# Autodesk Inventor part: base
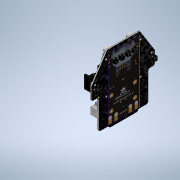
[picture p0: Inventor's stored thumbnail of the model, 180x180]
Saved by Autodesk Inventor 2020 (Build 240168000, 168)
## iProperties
Part Number: base
Material: Générique
Document SubType Name: Modeling
Designer: Buhl
Density: 1 g/cm^3
Appearance: Par défaut
Author: Buhl
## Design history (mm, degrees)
sketch "Esquisse1"
  geometry: L1 (0, 0)-(78, 0); L2 (78, -3)-(78, -44); L3 (14.627, -47)-(3, -47); L4 (0, -44)-(0, -3); L5 (-3, 0)-(-8.5, 0); L6 (-11.5, 3)-(-11.5, 19.102); L7 (-11.5, 20)-(88.5, 20); L8 (88.5, 19.135)-(88.5, 3); L9 (62.948, 58)-(15.117, 58); L10 (12.611, 56.649)-(-11.006, 20.75); L11 (88.04, 20.732)-(65.487, 56.597); L12 (81, 0)-(85.5, 0); L13 (18.5, -50)-(59.768, -50); L14 (75, -47)-(63.625, -47.035); A1 r 2 centre (86.5, 19.423) between (88.5, 19.423) and (88.193, 20.488); A2 r 2 centre (63.5, 56) between (65.193, 57.065) and (63.5, 58); A3 r 2 centre (14.578, 56) between (14.578, 58) and (12.907, 57.099); A4 r 2 centre (-9.5, 19.401) between (-11.171, 20.5) and (-11.5, 19.401); A5 r 2 centre (-9.5, 2) between (-11.5, 2) and (-9.5, 0); A6 r 3 centre (85.5, 19.135) between (88.5, 19.135) and (88.04, 20.732); A7 r 3 centre (62.948, 55) between (65.487, 56.597) and (62.948, 58); A8 r 3 centre (15.117, 55) between (15.117, 58) and (12.611, 56.649); A9 r 3 centre (-8.5, 19.102) between (-11.006, 20.75) and (-11.5, 19.102); A10 r 3 centre (-8.5, 3) between (-11.5, 3) and (-8.5, 0); A11 r 3 centre (-3, -3) between (0, -3) and (-3, 0); A12 r 3 centre (3, -44) between (0, -44) and (3, -47); A13 r 3 centre (75, -44) between (75, -47) and (78, -44); A14 r 3 centre (81, -3) between (81, 0) and (78, -3); A15 r 3 centre (85.5, 3) between (85.5, 0) and (88.5, 3); A16 r 2 centre (14.627, -49) between (16.564, -48.5) and (14.627, -47); A17 r 2 centre (63.632, -49.035) between (63.625, -47.035) and (61.7, -48.518); A18 r 2 centre (18.5, -48) between (16.564, -48.5) and (18.5, -50); A19 r 2 centre (59.768, -48) between (59.768, -50) and (61.7, -48.518); 8 further points
  constraints: 38 point on circle, 36 tangent, 33 point on line, 28 end point, 19 centre point, 14 equal radius, 4 horizontal, 4 parallel, 2 perpendicular
  dimensions: "d0" = 78 distance of point (78, -47) point (0, -47); "d1" = 47 distance of L1.end point (78, -47); "d2" = 100 distance of L7.start L7.end; "d3" = 11.5 distance between parallel lines of L6 L4; "d4" = 20 distance of point (-11.5, 0) L7.start; "d5" = 105 distance between parallel lines of L3 L9; "d6" = 50 distance of point (63.5, 58) point (13.5, 58); "d7" = 25 distance from line of point (13.5, 58) L6; "d8" = 2 radius of A1 (derived); "d9" = 3 radius of A6; "d10" = 3 radius of A14 (derived); "d247" = 3 distance between parallel lines of L3 L13; "d249" = 2 radius of A16 (derived)
extrude "Extrusion1" new body sketch "Esquisse1" distance "d11" = 1.6; taper "d12" = 0 deg
sketch "Esquisse2"
  geometry: L1 (-47, 3)-(-47, 75) reference; L2 (-44, 78)-(-3, 78) reference; L3 (-47, 3)-(-47, 75) reference; L4 (-47, 39)-(32.996, 39); L5 (-50, 18.5)-(-50, 59.768) reference; L6 (0, 81)-(0, 85.5) reference; L7 (3, 88.5)-(19.135, 88.5) reference; L8 (58, 62.948)-(58, 15.117) reference; L9 (20.732, 88.04)-(56.597, 65.487) reference; C1 r 1.5 at (19.402, 83.5); C2 r 1.5 at (46, 66.244); C3 r 1.5 at (-5, 66); C4 r 1.5 at (-32, 39); 3 further points
  constraints: 4 centre point, 2 end point, 1 horizontal, 1 midpoint, 1 point on line
  dimensions: "d13" = 3 diameter of C1; "d16" = 3 diameter of C2; "d18" = 3 diameter of C3; "d255" = 3 diameter of C4; "d256" = 18 distance from line of L5 C4.centre; "d257" = 12 distance from line of L2 C3.centre; "d258" = 5 distance from line of C3.centre L6; "d259" = 5 distance from line of L7 C1.centre; "d260" = 12 distance from line of L8 C2.centre; "d261" = 5 distance from line of L9 C2.centre
extrude "Extrusion2" cut sketch "Esquisse2" distance "d21" = 1.6; taper "d22" = 0 deg
sketch "Esquisse3"
  geometry: C1 r 1.5 at (-5, 66) reference; C2 r 1.5 at (46, 66.244) reference; C3 r 1.5 at (19.402, 83.5) reference; C4 r 2.75 at (-5, 66); C5 r 2.75 at (46, 66.244); C6 r 1.5 at (19.402, 83.5) reference; C7 r 2.75 at (19.402, 83.5); C8 r 1.5 at (-32, 39) reference; C9 r 2.75 at (-32, 39); 1 further point
  constraints: 4 centre point, 4 coincident
  dimensions: "d23" = 5.5 diameter of C4; "d24" = 5.5 diameter of C5; "d25" = 5.5 diameter of C7; "d262" = 5.5 diameter of C9
extrude "Extrusion3" join sketch "Esquisse3" distance "d26" = 3; taper "d27" = 0 deg
sketch "Esquisse4"
  geometry: L1 (-26, 10.532)-(-32, 10.532); L2 (-32, 10.532)-(-32, 67.532); L3 (-32, 67.532)-(-26, 67.532); L4 (-26, 67.532)-(-26, 10.532); L5 (-58, 62.948)-(-58, 15.117) reference; L6 (-3.465, 3.627)-(-1.465, 3.627); L7 (-1.465, 3.627)-(-1.465, 54.627); L8 (-1.465, 54.627)-(-3.465, 54.627); L9 (-3.465, 54.627)-(-3.465, 3.627); L10 (-58, 39.032)-(-14.636, 39.032); 2 further points
  constraints: 18 end point, 4 parallel, 3 horizontal, 2 midpoint, 2 perpendicular, 1 point on line
  dimensions: "d28" = 32 distance between parallel lines of L4 L5; "d29" = 6 distance of L2.end L3.end; "d30" = 51 distance of L8.end L6.start; "d31" = 57 distance between parallel lines of L3 L1; "d32" = 2 distance between parallel lines of L7 L9
extrude "Extrusion4" join sketch "Esquisse4" distance "d33" = 12.2; taper "d34" = 0 deg
sketch "Esquisse5"
  geometry: 1 further point
sketch "Esquisse6"
  geometry: 1 further point
node "Plan de construction1"
node "Plan de construction3"
mirror "Symétrie1"
sketch "Esquisse9"
  geometry: L1 (-3, 0)-(-44, 0) reference; L2 (-32, 0)-(-17, 0); L3 (-17, 0)-(-17, 24); L4 (-17, 24)-(-32, 24); L5 (-32, 24)-(-32, 0); L6 (-47, 3)-(-47, 75) reference; 1 further point
  constraints: 8 end point, 2 parallel, 1 horizontal, 1 perpendicular, 1 point on line
  dimensions: "d54" = 15 distance of L4.end L3.end; "d55" = 24 distance of L3.end L2.end; "d56" = 15 distance between parallel lines of L6 L5
extrude "Extrusion8" join sketch "Esquisse9" distance "d57" = 11; taper "d58" = 0 deg
sketch "Esquisse10"
  geometry: L1 (0, 12)-(-11, 12) reference; L2 (0, 12)-(0, 27) reference; L3 (-11, 12)-(0, 27); C1 r 1.5 at (-5.5, 19.5); 1 further point
  constraints: 2 end point, 1 centre point, 1 midpoint
  dimensions: "d59" = 3 diameter of C1
extrude "Extrusion9" cut sketch "Esquisse10" distance "d60" = 10; taper "d61" = 0 deg
sketch "Esquisse11"
  geometry: L1 (-36, 41.532)-(-42, 41.532); L2 (-42, 41.532)-(-42, 46.532); L3 (-42, 46.532)-(-36, 46.532); L4 (-36, 46.532)-(-36, 41.532); L5 (-58, 62.948)-(-58, 15.117) reference; L6 (-15, 82.5)-(-9, 82.5); L7 (-9, 82.5)-(-9, 87.5); L8 (-9, 87.5)-(-15, 87.5); L9 (-15, 87.5)-(-15, 82.5); L10 (0, 81)-(0, 85.5) reference; L11 (-3, 88.5)-(-19.135, 88.5) reference; L12 (-61.191, 39.032)-(-11.173, 39.032); L13 (-42, 51.532)-(-36, 51.532); L14 (-36, 51.532)-(-36, 56.532); L15 (-36, 56.532)-(-42, 56.532); L16 (-42, 56.532)-(-42, 51.532); 2 further points
  constraints: 26 end point, 6 parallel, 4 horizontal, 3 perpendicular, 1 midpoint, 1 point on line
  dimensions: "d63" = 5 distance of L1.end L2.end; "d64" = 6 distance of L2.end L3.end; "d65" = 22 distance between parallel lines of L4 L5; "d271" = 6 distance of L7.end L8.end; "d272" = 5 distance of L6.end L7.end; "d273" = 9 distance between parallel lines of L10 L7; "d274" = 6 distance between parallel lines of L11 L6; "d275" = 2.5 distance between parallel lines of L1 L12; "d276" = 6 distance of L15.end L14.end; "d277" = 5 distance of L14.end L13.end; "d278" = 5 distance between parallel lines of L13 L3
extrude "Extrusion10" join sketch "Esquisse11" distance "d66" = 5; taper "d67" = 0 deg
mirror "Symétrie3"
sketch "Esquisse13"
  geometry: L1 (-52.453, 14.685)-(-52.453, 64.242); L2 (-52.453, 64.242)-(45.75, 64.242); L3 (45.75, 64.242)-(45.75, 14.685); L4 (45.75, 14.685)-(-52.453, 14.685); 1 further point; 1 other entity
  constraints: 2 other
  node "Image1"
sketch "Esquisse14"
  geometry: L1 (42.128, 71.823)-(42.128, 5.773); L2 (42.128, 5.773)-(-45.058, 5.773); L3 (-45.058, 5.773)-(-45.058, 71.823); L4 (-45.058, 71.823)-(42.128, 71.823); 1 further point; 1 other entity
  constraints: 2 end point, 1 other
  node "Image2"
sketch "Esquisse16"
  geometry: L1 (-32, 24)-(-32, 0) reference; L2 (-32, 0)-(-17, 0) reference; L3 (-32, 0)-(-29.5, 0); L4 (-29.5, 0)-(-29.5, 7); L5 (-29.5, 7)-(-32, 7); L6 (-32, 7)-(-32, 0); L7 (-17, 0)-(-19.5, 0); L8 (-19.5, 0)-(-19.5, 7); L9 (-19.5, 7)-(-17, 7); L10 (-17, 7)-(-17, 0); L11 (-32, 54)-(-32, 78) reference; L12 (-32, 78)-(-17, 78) reference; L13 (-17, 78)-(-17, 54) reference; L14 (-32, 78)-(-29.5, 78); L15 (-29.5, 78)-(-29.5, 71); L16 (-29.5, 71)-(-32, 71); L17 (-32, 71)-(-32, 78); L18 (-17, 78)-(-19.5, 78); L19 (-19.5, 78)-(-19.5, 71); L20 (-19.5, 71)-(-17, 71); L21 (-17, 71)-(-17, 78); 1 further point
  constraints: 32 end point, 8 parallel, 4 horizontal, 4 perpendicular, 2 point on line
  dimensions: "d186" = 2.5 distance of L4.end L5.end; "d187" = 2.5 distance of L8.end L9.end; "d188" = 7 distance of L3.end L4.end; "d189" = 7 distance of L18.end L19.end
extrude "Extrusion13" cut sketch "Esquisse16" distance "d190" = 11; taper "d191" = 0 deg
node "Plan de construction2"
sketch "Esquisse12"
  geometry: C1 r 1.683 at (-14.287, 36.5); C2 r 1.703 at (-9.745, 36.5); 1 further point
  constraints: 2 centre point
extrude "Extrusion11" cut sketch "Esquisse12" distance "d68" = 0.5; taper "d69" = 0 deg
mirror "Symétrie2"
sketch "Esquisse17"
  geometry: L1 (-44, 78)-(-3, 78) reference; L2 (-3, 0)-(-44, 0) reference; L3 (0, 78)-(20, 78); L4 (20, 78)-(20, 0); L5 (20, 0)-(0, 0); L6 (0, 0)-(0, 78); 3 further points
  constraints: 8 end point, 2 parallel, 1 horizontal, 1 perpendicular
  dimensions: "d222" = 20 distance of L4.end L5.end
extrude "Extrusion14" join sketch "Esquisse17" distance "d223" = 21; taper "d224" = 0 deg
sketch "Esquisse18"
  geometry: L1 (0, 0)-(0, 78) reference; L2 (0, 0)-(21, 0) reference; L3 (21, 78)-(21, 0) reference; L4 (0, 78)-(21, 78) reference; L5 (22.117, 76.165)-(15.78, 76.165); L6 (15.78, 1.988)-(22.117, 1.988); L7 (22.117, 1.988)-(22.117, 76.165); L8 (0, 24)-(11, 24) reference; L9 (8.573, 52.434)-(8.573, 24); L10 (8.573, 24)-(13.171, 24); L11 (13.171, 52.434)-(13.171, 64.289); L12 (13.171, 64.289)-(15.78, 69.704); L13 (13.171, 24)-(13.171, 13.419); L14 (13.171, 13.419)-(15.78, 7.082); L15 (15.78, 76.165)-(15.78, 69.704); L16 (15.78, 7.082)-(15.78, 1.988); L17 (13.171, 52.434)-(8.573, 52.434); 2 further points
  constraints: 24 end point, 4 parallel, 3 perpendicular, 2 horizontal, 2 point on line, 1 vertical
extrude "Extrusion15" cut sketch "Esquisse18" distance "d265" = 20; taper "d266" = 0 deg
sketch "Esquisse19"
  geometry: L1 (21, 20)-(0, 20) reference; L2 (0, 20)-(21, 0); L3 (0, 0)-(21, 20); C1 r 9.355 at (9.339, 10)
  constraints: 4 end point, 1 centre point
extrude "Extrusion16" cut sketch "Esquisse19" stored distance "d267" = 20; taper "d268" = 0 deg
sketch "Esquisse20"
  geometry: L1 (30.205, 66.59)-(27.421, 66.59); L2 (27.421, 66.59)-(27.421, 11.814); L3 (27.421, 11.814)-(30.205, 11.814); L4 (30.205, 11.814)-(30.205, 66.59); 1 further point
  constraints: 8 end point, 2 parallel, 1 horizontal, 1 perpendicular
extrude "Extrusion17" cut sketch "Esquisse20" distance "d269" = 10; taper "d270" = 0 deg
mirror "Symétrie4"
node "Plan de construction5"
sketch "Esquisse22"
  geometry: L1 (0, -26.617)-(1.6, -26.617) reference; L2 (0, 73.383)-(1.6, 73.383) reference; C1 r 5 at (-5.411, 5.383); C2 r 5 at (-5.411, 41.383); 1 further point
  constraints: 2 centre point
  dimensions: "d280" = 10 diameter of C1; "d281" = 10 diameter of C2; "d282" = 32 distance from line of L1 C1.centre; "d283" = 32 distance from line of C2.centre L2
extrude "Extrusion18" join sketch "Esquisse22" distance "d284" = 2; taper "d285" = 0 deg
sketch "Esquisse23"
  geometry: C1 r 4.5 at (0, 0); C2 r 5 at (0, 36) reference; C3 r 4.5 at (0, 36); 1 further point
  constraints: 2 centre point, 1 coincident
  dimensions: "d286" = 9 diameter of C1; "d287" = 9 diameter of C3
extrude "Extrusion19" join sketch "Esquisse23" distance "d288" = 11; taper "d289" = 0 deg
fillet "Congé1" dims "d290" = 4.5
node "Solide1"
node "Boucle projetée4"
node "Plan de construction4"
node "Boucle projetée5"
other parameters: "d35" = -39, "d231" = -39, "d279" = -15
